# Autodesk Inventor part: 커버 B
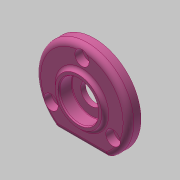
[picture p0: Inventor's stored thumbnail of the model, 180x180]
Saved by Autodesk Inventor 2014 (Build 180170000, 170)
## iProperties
Created: 2020-04
Part Number: 커버 B
Material: 알루미늄 6061
Document SubType Name: Modeling
Designer: mduedu
Density: 2.71 g/cm^3
Appearance: Pink
Mass: 33.6764 g
Surface Area: 62.2842 cm^2
Volume: 12.4267 cm^3
Author: mduedu
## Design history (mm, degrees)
sketch "스케치1"
  geometry: C1 r 26 at (0, 0); 1 further point
  constraints: 1 centre point, 1 coincident
  dimensions: "d0" = 52 diameter of C1
extrude "돌출1" new body sketch "스케치1" distance "d1" = 7; taper "d2" = 0 deg
sketch "스케치2"
  geometry: L1 (-14.62, -21.5)-(14.62, -21.5); A1 r 26 centre (0, 0) between (-14.62, -21.5) and (14.62, -21.5) reference; 1 further point
  constraints: 2 end point, 2 point on circle, 1 horizontal
  dimensions: "d3" = 21.5 distance from line of L1 point (0, 0)
extrude "돌출2" cut sketch "스케치2" stored distance "d4" = 7; taper "d5" = 0 deg
sketch "스케치6"
  geometry: C1 r 13 at (0, 0); 1 further point
  constraints: 1 centre point, 1 coincident
  dimensions: "d29" = 26 diameter of C1
extrude "돌출5" join sketch "스케치6" distance "d30" = 2; taper "d31" = 0 deg
fillet "모깎기1" dims "d6" = 3
fillet "모깎기2" dims "d7" = 3
fillet "모깎기4" dims "d33" = 2
sketch "스케치3" dims "d8" = 40
  geometry: 3 further points
  constraints: 2 vertical alignment, 1 coincident, 2 other
hole "구멍1" sketch "스케치3" at (0, 20) diameter "d9" = 4.5; stored, may be unused: countersink angle "d13" = 90 deg, drill point angle "d15" = 118 deg; dims "d10" = 6, "d11" = 8, "d12" = 4.4, "d14" = 8
sketch "스케치4"
  geometry: C1 r 14 at (0, 0); 1 further point
  constraints: 1 centre point, 1 coincident
  dimensions: "d19" = 28 diameter of C1
extrude "돌출3" join sketch "스케치4" distance "d20" = 4; taper "d21" = 0 deg
sketch "스케치5"
  geometry: C1 r 12 at (0, 0); 1 further point
  constraints: 1 centre point, 1 coincident
  dimensions: "d22" = 24 diameter of C1
extrude "돌출4" cut sketch "스케치5" distance "d23" = 3; taper "d24" = 0 deg
fillet "모깎기3" dims "d25" = 3
chamfer "모따기1" distance "d26" = 0.5; stored, may be unused: second distance "d27" = 2, angle "d28" = 45 deg
sketch "스케치7"
  geometry: 2 further points
  constraints: 1 coincident
hole "구멍2" sketch "스케치7" at (0, 0) diameter "d34" = 12; stored, may be unused: countersink angle "d38" = 90 deg, drill point angle "d40" = 118 deg; dims "d35" = 6, "d36" = 22, "d37" = 7.3, "d39" = 8
fillet "모깎기5" dims "d41" = 0.3
chamfer "모따기2" distance "d42" = 0.7; stored, may be unused: second distance "d43" = 2, angle "d44" = 30 deg
node "솔리드1"
pattern_circular "원형 패턴1" dims angle "d17" = 360 deg
node "투영된 루프1"
